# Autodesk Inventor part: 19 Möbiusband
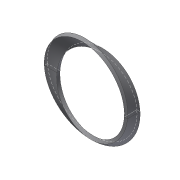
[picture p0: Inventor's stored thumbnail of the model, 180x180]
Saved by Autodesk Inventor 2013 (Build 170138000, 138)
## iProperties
Created: 2012-10
Part Number: 19 Möbiusband
Material: Allgemein
Vendor: www.inventor-faq.de
Document SubType Name: Modeling
Designer: Administrator
Manufacturer: www.inventor-faq.de
Density: 1 g/cm^3
RuleStatus: InUse
AfterDocOpen0: inventorfaq
BeforeDocSave0: inventorfaq
Author: Administrator
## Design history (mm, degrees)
sketch "Querschnitt"
  geometry: L1 (-5, -1.25)-(5, -1.25); L2 (5, -1.25)-(5, 1.25); L3 (5, 1.25)-(-5, 1.25); L4 (-5, 1.25)-(-5, -1.25); L5 (-5, -1.25)-(5, 1.25); L6 (5, -1.25)-(-5, 1.25); 1 further point
  constraints: 12 end point, 2 midpoint, 2 parallel, 1 horizontal, 1 perpendicular
  dimensions: "d0" = 10 distance of L3.end L2.end; "d1" = 2.5 distance of L2.end L1.end (= 0.25 x d0)
feature "Spirale1" pitch "d2" = 10; turns "d4" = 0.25; dims "d5" = 0, angle "d6" = 90 deg, angle "d7" = 90 deg, "d8" = 0, "d9" = 0, "Höhe_Spirale" = 100
sketch "Biegelinie"
  geometry: L1 (-14, 0)-(14, 0) reference; 1 further point
feature "Spirale2" pitch "d10" = 10; turns "d12" = 0.25; dims "d11" = 100 (= Höhe_Spirale), "d13" = 0, angle "d14" = 90 deg, angle "d15" = 90 deg, "d16" = 0, "d17" = 0
feature "Biegungsteil1" dims "d18" = 180 deg, "d19" = 100 (= Höhe_Spirale)
feature "Biegungsteil2 (nicht exakt 180 Grad!)" dims "d20" = 31.41591, "d21" = 100 (= Höhe_Spirale)
node "Volumenkörper1"
